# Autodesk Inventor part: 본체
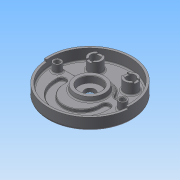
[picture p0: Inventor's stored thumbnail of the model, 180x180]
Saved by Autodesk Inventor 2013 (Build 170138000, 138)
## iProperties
Created: 2015-04
Part Number: 본체
Material: 일반
Document SubType Name: Modeling
Designer: Administrator
Density: 1 g/cm^3
Author: Administrator
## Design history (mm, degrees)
sketch "스케치1"
  geometry: C1 r 95 at (0, 0); 1 further point
  constraints: 1 centre point, 1 coincident
  dimensions: "d0" = 190 diameter of C1
extrude "돌출1" new body sketch "스케치1" distance "d1" = 32; taper "d2" = 0 deg
sketch "스케치2"
  geometry: C1 r 95 at (0, 0) reference; C2 r 90 at (0, 0)
  constraints: 1 centre point, 1 coincident
  dimensions: "d3" = 180 diameter of C2
extrude "돌출2" cut sketch "스케치2" distance "d4" = 25; taper "d5" = 0 deg
sketch "스케치4"
  geometry: C1 r 90 at (0, 0) reference; C2 r 15 at (-40, 52)
  constraints: 1 centre point
  dimensions: "d8" = 30 diameter of C2; "d9" = 52 vertical distance of C1.centre C2.centre; "d10" = 40 horizontal distance of C1.centre C2.centre
extrude "돌출3" join sketch "스케치4" distance "d11" = 25; taper "d12" = 0 deg
sketch "스케치5"
  geometry: C1 r 15 at (0, 0) reference; C2 r 10 at (0, 0); 1 further point
  constraints: 1 centre point, 1 coincident
  dimensions: "d13" = 20 diameter of C2
extrude "돌출4" cut sketch "스케치5" stored distance "d14" = 18; taper "d15" = 0 deg
sketch "스케치6"
  geometry: L1 (-6, 13.748)-(-6, -13.748); L2 (6, 13.748)-(6, -13.748); C1 r 10 at (0, 0) reference; A1 r 15 centre (0, 0) between (-6, 13.748) and (-6, -13.748) reference; 1 further point
  constraints: 4 end point, 4 point on circle, 1 parallel, 1 vertical
  dimensions: "d16" = 6 distance from line of C1.centre L1; "d17" = 6 distance from line of L2 C1.centre
extrude "돌출5" cut sketch "스케치6" distance "d18" = 3; taper "d19" = 0 deg
sketch "스케치7"
  geometry: C1 r 90 at (0, 0) reference; C2 r 15 at (40, 52)
  constraints: 1 centre point
  dimensions: "d20" = 30 diameter of C2; "d21" = 40 horizontal distance of C1.centre C2.centre; "d22" = 52 vertical distance of C1.centre C2.centre
extrude "돌출6" join sketch "스케치7" distance "d23" = 25; taper "d24" = 0 deg
sketch "스케치9"
  geometry: C1 r 15 at (0, 0) reference; C2 r 10 at (0, 0); 1 further point
  constraints: 1 centre point, 1 coincident
  dimensions: "d30" = 20 diameter of C2
extrude "돌출8" cut sketch "스케치9" stored distance "d31" = 3; taper "d32" = 0 deg
sketch "스케치8"
  geometry: L1 (-13.748, -6)-(13.748, -6); L2 (-13.748, 6)-(13.748, 6); A1 r 15 centre (0, 0) between (-13.748, -6) and (13.748, -6) reference; 1 further point
  constraints: 4 end point, 4 point on circle, 1 horizontal, 1 parallel
  dimensions: "d25" = 6 distance from line of A1.centre L1; "d27" = 6 distance from line of L2 A1.centre
extrude "돌출7" cut sketch "스케치8" distance "d28" = 3; taper "d29" = 0 deg
sketch "스케치10"
  geometry: L1 (-76.916, 12)-(-47.117, 12); L2 (47.117, 12)-(76.916, 12); C1 r 90 at (0, 0) reference; A1 r 90 centre (0, 0) between (-86.53, 24.75) and (86.53, 24.75); A2 r 42 centre (0, 0) between (38.056, 17.769) and (-38.056, 17.769); A3 r 10 centre (-47.117, 22) between (-47.117, 12) and (-38.056, 17.769); A4 r 10 centre (-76.916, 22) between (-86.53, 24.75) and (-76.916, 12); A5 r 90 centre (0, 0) between (-86.53, 24.75) and (86.53, 24.75) reference; A6 r 10 centre (47.117, 22) between (38.056, 17.769) and (47.117, 12); A7 r 10 centre (76.916, 22) between (76.916, 12) and (86.53, 24.75)
  constraints: 14 point on circle, 12 tangent, 6 centre point, 4 end point, 2 coincident, 2 horizontal, 1 concentric
  dimensions: "d34" = 84 diameter of A2; "d36" = 20 diameter of A3; "d37" = 20 diameter of A4; "d38" = 20 diameter of A6; "d39" = 20 diameter of A7; "d40" = 29.79866 distance of L1.start L1.end
extrude "돌출9" join sketch "스케치10" distance "d41" = 7; taper "d42" = 0 deg
sketch "스케치11"
  geometry: C1 r 35 at (0, 0); A1 r 90 centre (0, 0) between (-86.53, 24.75) and (86.53, 24.75) reference
  constraints: 1 centre point, 1 coincident
  dimensions: "d43" = 70 diameter of C1
extrude "돌출10" join sketch "스케치11" distance "d44" = 10; taper "d45" = -10 deg
sketch "스케치12"
  geometry: C1 r 33.237 at (0, 0) reference; C2 r 25 at (0, 0)
  constraints: 1 centre point, 1 coincident
  dimensions: "d46" = 50 diameter of C2
extrude "돌출11" cut sketch "스케치12" distance "d47" = 15; taper "d48" = 0 deg
sketch "스케치13"
  geometry: C1 r 25 at (0, 0) reference; C2 r 11.5 at (0, 0)
  constraints: 1 centre point, 1 coincident
  dimensions: "d49" = 23 diameter of C2
extrude "돌출12" cut sketch "스케치13" stored distance "d50" = 15; taper "d51" = 0 deg
sketch "스케치14"
  geometry: L1 (-76.916, 12)-(-47.117, 12) reference; L2 (47.117, 12)-(76.916, 12) reference; L3 (-76.916, 12)-(-47.117, 12) reference; L4 (47.117, 12)-(76.916, 12) reference; L5 (-59, -14)-(-59, -19); L6 (-41, -14)-(-41, -19); L7 (41, -14)-(41, -19); L8 (59, -14)-(59, -19); C1 r 35 at (0, 0) reference; C2 r 25 at (0, 0) reference; C3 r 35 at (0, 0) reference; C4 r 10 at (40, 52) reference; C5 r 15 at (40, 52) reference; C6 r 10 at (-40, 52) reference; C7 r 15 at (-40, 52) reference; C8 r 95 at (0, 0) reference; C9 r 25 at (0, 0) reference; C10 r 35 at (0, 0) reference; C11 r 10 at (40, 52) reference; C12 r 15 at (40, 52) reference; C13 r 10 at (-40, 52) reference; C14 r 15 at (-40, 52) reference; C15 r 95 at (0, 0) reference; A1 r 10 centre (76.916, 22) between (76.916, 12) and (86.53, 24.75) reference; A2 r 90 centre (0, 0) between (86.53, 24.75) and (-86.53, 24.75) reference; A3 r 10 centre (-76.916, 22) between (-86.53, 24.75) and (-76.916, 12) reference; A4 r 10 centre (-47.117, 22) between (-47.117, 12) and (-38.056, 17.769) reference; A5 r 42 centre (0, 0) between (38.056, 17.769) and (-38.056, 17.769) reference; A6 r 10 centre (47.117, 22) between (38.056, 17.769) and (47.117, 12) reference; A7 r 90 centre (0, 0) between (-86.53, 24.75) and (86.53, 24.75) reference; A8 r 10 centre (76.916, 22) between (76.916, 12) and (86.53, 24.75) reference; A9 r 90 centre (0, 0) between (86.53, 24.75) and (-86.53, 24.75) reference; A10 r 10 centre (-76.916, 22) between (-86.53, 24.75) and (-76.916, 12) reference; A11 r 10 centre (-47.117, 22) between (-47.117, 12) and (-38.056, 17.769) reference; A12 r 42 centre (0, 0) between (38.056, 17.769) and (-38.056, 17.769) reference; A13 r 10 centre (47.117, 22) between (38.056, 17.769) and (47.117, 12) reference; A14 r 90 centre (0, 0) between (-86.53, 24.75) and (86.53, 24.75) reference; A15 r 9 centre (-50, -14) between (-41, -14) and (-59, -14); A16 r 9 centre (50, -14) between (59, -14) and (41, -14); A17 r 41 centre (0, -19) between (-41, -19) and (41, -19); A18 r 59 centre (0, -19) between (-59, -19) and (59, -19)
  constraints: 8 end point, 8 point on circle, 8 tangent, 4 centre point, 1 coincident, 1 vertical alignment
  dimensions: "d53" = 19 distance of A18.centre C1.centre; "d55" = 18 diameter of A15; "d56" = 14 vertical distance of A15.centre C1.centre; "d57" = 50 horizontal distance of C1.centre A15.centre; "d58" = 18 diameter of A16; "d59" = 14 vertical distance of C1.centre A16.centre; "d60" = 50 horizontal distance of A16.centre C1.centre; "d61" = 59 radius of A18; "d62" = 41 radius of A17
extrude "돌출13" cut sketch "스케치14" distance "d63" = 7; taper "d64" = 0 deg
sketch "스케치15"
  geometry: C1 r 35 at (0, 0) reference; C2 r 9 at (-74, 0); C3 r 9 at (74, 0)
  constraints: 2 centre point, 2 horizontal alignment
  dimensions: "d65" = 18 diameter of C2; "d66" = 18 diameter of C3; "d67" = 74 distance of C1.centre C2.centre; "d68" = 74 distance of C3.centre C1.centre
extrude "돌출14" join sketch "스케치15" stored distance "d69" = 7; taper "d70" = 0 deg
sketch "스케치16"
  geometry: C1 r 9 at (-74, 0) reference; C2 r 9 at (74, 0) reference; 2 further points
  constraints: 2 coincident
hole "구멍1" sketch "스케치16" at (-74, 0), (74, 0) diameter "d71" = 11; stored, may be unused: countersink angle "d75" = 90 deg, drill point angle "d77" = 118 deg; dims "d72" = 6, "d73" = 18, "d74" = 11, "d76" = 8
sketch "스케치17"
  geometry: L1 (0, 0)-(-94.638, -8.28); L2 (0, 0)-(94.638, -8.28); L3 (0, 0)-(42.605, 0); L4 (0, 0)-(-4.864, -0.426); L5 (0, 0)-(-42.623, 0); C1 r 90 at (0, 0) reference; A1 r 95 centre (0, 0) between (-94.638, -8.28) and (94.638, -8.28) reference; A2 r 90 centre (0, 0) between (-89.658, -7.844) and (89.658, -7.844)
  constraints: 10 end point, 4 point on circle, 3 point on line, 2 coincident, 1 centre point, 1 collinear, 1 concentric, 1 horizontal
  dimensions: "d78" = 5 deg angle of L5 L1; "d79" = 5 deg angle of L3 L2
extrude "돌출15" cut sketch "스케치17" distance "d80" = 5; taper "d81" = 0 deg
sketch "스케치18"
  geometry: L1 (0, 0)-(50.912, -50.912); L2 (0, 0)-(0, -81.344); L3 (0, 0)-(-50.912, -50.912); C1 r 95 at (0, 0) reference; C2 r 51 at (0, 0); A1 r 72 centre (0, 0) between (50.912, -50.912) and (-50.912, -50.912)
  constraints: 6 end point, 2 centre point, 2 coincident, 2 point on circle, 1 vertical
  dimensions: "d82" = 51 radius of C2; "d83" = 72 radius of A1; "d84" = 45 deg angle of L1 L2; "d85" = 45 deg angle of L2 L3
extrude "돌출16" join sketch "스케치18" distance "d86" = 5; taper "d87" = 0 deg
sketch "스케치19"
  geometry: C1 r 11.5 at (0, 0); A1 r 11.5 centre (0, 0) between (-8.132, -8.132) and (8.132, -8.132) reference
  constraints: 1 centre point, 1 coincident, 1 concentric
extrude "돌출17" cut sketch "스케치19" stored distance "d88" = 0; taper "d89" = 0 deg
sketch "스케치20"
  geometry: C1 r 51 at (0, 0); A1 r 72 centre (0, 0) between (-50.912, -50.912) and (50.912, -50.912) reference
  constraints: 1 centre point, 1 coincident
  dimensions: "d90" = 51 radius of C1
extrude "돌출18" cut sketch "스케치20" distance "d91" = 5; taper "d92" = 0 deg
fillet "모깎기1" dims "d93" = 5
fillet "모깎기2" dims "d94" = 5
fillet "모깎기3" dims "d95" = 3
sketch "스케치22"
  geometry: C1 r 68 at (0, 0); A1 r 67 centre (0, 0) between (-43.709, -50.78) and (43.709, -50.78) reference
  constraints: 1 centre point, 1 coincident, 1 other
  dimensions: "d98" = 68 radius of C1
feature "엠보싱1" sketch "스케치22" dims "d99" = 0.5, "d100" = 0
fillet "모깎기4" dims "d101" = 5
fillet "모깎기5" dims "d102" = 1
chamfer "모따기1" distance "d103" = 1; stored, may be unused: second distance "d104" = 2, angle "d105" = 45 deg
chamfer "모따기2" distance "d106" = 1; stored, may be unused: second distance "d107" = 2, angle "d108" = 45 deg
fillet "모깎기6" dims "d109" = 3
node "솔리드1"
node "절단 모서리 투영1"
node "절단 모서리 투영2"
other parameters: "d35" = 12, "d52" = 118, "d54" = 82
